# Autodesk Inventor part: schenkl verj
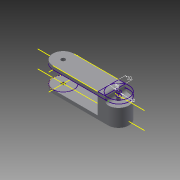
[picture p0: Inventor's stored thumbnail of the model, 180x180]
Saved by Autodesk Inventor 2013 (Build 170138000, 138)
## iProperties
Created: 2012-11
Part Number: schenkl verj
Material: Allgemein
Document SubType Name: Modeling
Designer: macuser
Density: 1 g/cm^3
Author: macuser
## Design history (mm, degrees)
sketch "Skizze1"
  geometry: L1 (0, -42)-(0, 42) reference; L2 (-74, 0)-(234, 0) reference; L3 (0, 30)-(160, 30); L4 (0, -30)-(160, -30); C1 r 6 at (0, 0); C2 r 6 at (160, 0); A1 r 30 centre (0, 0) between (0, 30) and (0, -30); A2 r 30 centre (160, 0) between (160, 30) and (160, -30); 1 further point
  constraints: 4 centre point, 4 end point, 4 point on circle, 2 coincident, 2 parallel, 2 point on line, 2 tangent
  dimensions: "d0" = 60 diameter of A1; "d1" = 60 diameter of A2; "d2" = 0 distance from line of L1 A1.centre; "d3" = 160 distance of A2.centre point (0, 0); "d4" = 12 diameter of C1; "d5" = 12 diameter of C2
extrude "Extrusion1" new body sketch "Skizze1" distance "d6" = 10; taper "d7" = 0 deg
sketch "Skizze2"
  geometry: L1 (0, -42)-(0, 42) reference; L2 (-74, 0)-(234, 0) reference; L3 (5, 30)-(155, 30); L4 (5, 30)-(5, 25); L5 (5, 25)-(155, 25); L6 (155, 25)-(155, 30); C1 r 30 at (0, 0); A1 r 30 centre (0, 0) between (0, 30) and (0, -30) reference
  constraints: 8 end point, 2 parallel, 1 centre point, 1 coincident, 1 perpendicular
  dimensions: "d8" = 150 distance of L3.start L3.end; "d9" = 5 distance from line of L1 L3.start; "d12" = 5 distance of L3.start L4.end; "d13" = 30 distance between parallel lines of L2 L3; "d31" = 5 distance of L5.end L3.end; "d44" = 60 diameter of C1
extrude "Extrusion5" join sketch "Skizze2" distance "d32" = 50; taper "d33" = 0 deg
sketch "Skizze4"
  geometry: L1 (0, -42)-(0, 42) reference; L2 (-74, 0)-(234, 0) reference; L3 (0, 30)-(160, 30); L4 (0, -30)-(160, -30); C1 r 6 at (0, 0); C2 r 6 at (160, 0); A1 r 30 centre (0, 0) between (0, 30) and (0, -30); A2 r 30 centre (160, 0) between (160, 30) and (160, -30); 1 further point
  constraints: 5 point on circle, 4 centre point, 4 end point, 3 coincident, 2 point on line, 2 tangent
  dimensions: "d34" = 60 diameter of A1; "d35" = 60 diameter of A2; "d36" = 0 distance from line of L2 A2.centre; "d37" = 160 distance of A1.centre A2.centre; "d38" = 12 diameter of C1; "d39" = 12 diameter of C2
extrude "Extrusion6" join sketch "Skizze4" distance "d40" = 10; taper "d41" = 0 deg
extrude "Extrusion7" cut sketch "Skizze4" distance "d42" = 10; taper "d43" = 0 deg
sketch "Skizze5"
  geometry: C1 r 6 at (0, 0) reference; C2 r 32.5 at (0, 0)
  constraints: 1 centre point, 1 coincident
  dimensions: "d46" = 65 diameter of C2
extrude "Extrusion8" cut sketch "Skizze5" distance "d47" = 50; taper "d48" = 0 deg
sketch "Skizze6"
  geometry: C1 r 6 at (160, 0) reference; C2 r 32.5 at (160, 0)
  constraints: 1 centre point, 1 coincident
  dimensions: "d50" = 65 diameter of C2
extrude "Extrusion9" cut sketch "Skizze6" distance "d51" = 50; taper "d52" = 0 deg
sketch "Skizze7"
  geometry: L1 (130, 30)-(130, -30); L2 (130, 30)-(160, 30); L3 (130, -30)-(160, -30); L4 (0, -30)-(160, -30) reference; L5 (160, 30)-(0, 30) reference; L6 (150, 30)-(150, -30); C1 r 6 at (160, 0) reference; C2 r 6 at (160, 0); A1 r 30 centre (160, 0) between (160, -30) and (160, 30) reference; A2 r 30 centre (160, 0) between (150, 28.284) and (150, -28.284); A3 r 30 centre (160, 0) between (160, -30) and (160, 30)
  constraints: 10 end point, 4 point on circle, 4 point on line, 3 centre point, 3 tangent, 2 coincident, 1 parallel, 1 perpendicular, 1 vertical
  dimensions: "d54" = 12 diameter of C2; "d59" = 20 distance between parallel lines of L6 L1; "d60" = 30 radius of A2
extrude "Extrusion11" join sketch "Skizze7" distance "d57" = 60; taper "d58" = 0 deg
extrude "Extrusion12" cut sketch "Skizze7" distance "d61" = 20; taper "d62" = 0 deg
fillet "Rundung1" dims "d63" = 10
fillet "Rundung2" dims "d64" = 10
node "Volumenkörper1"
